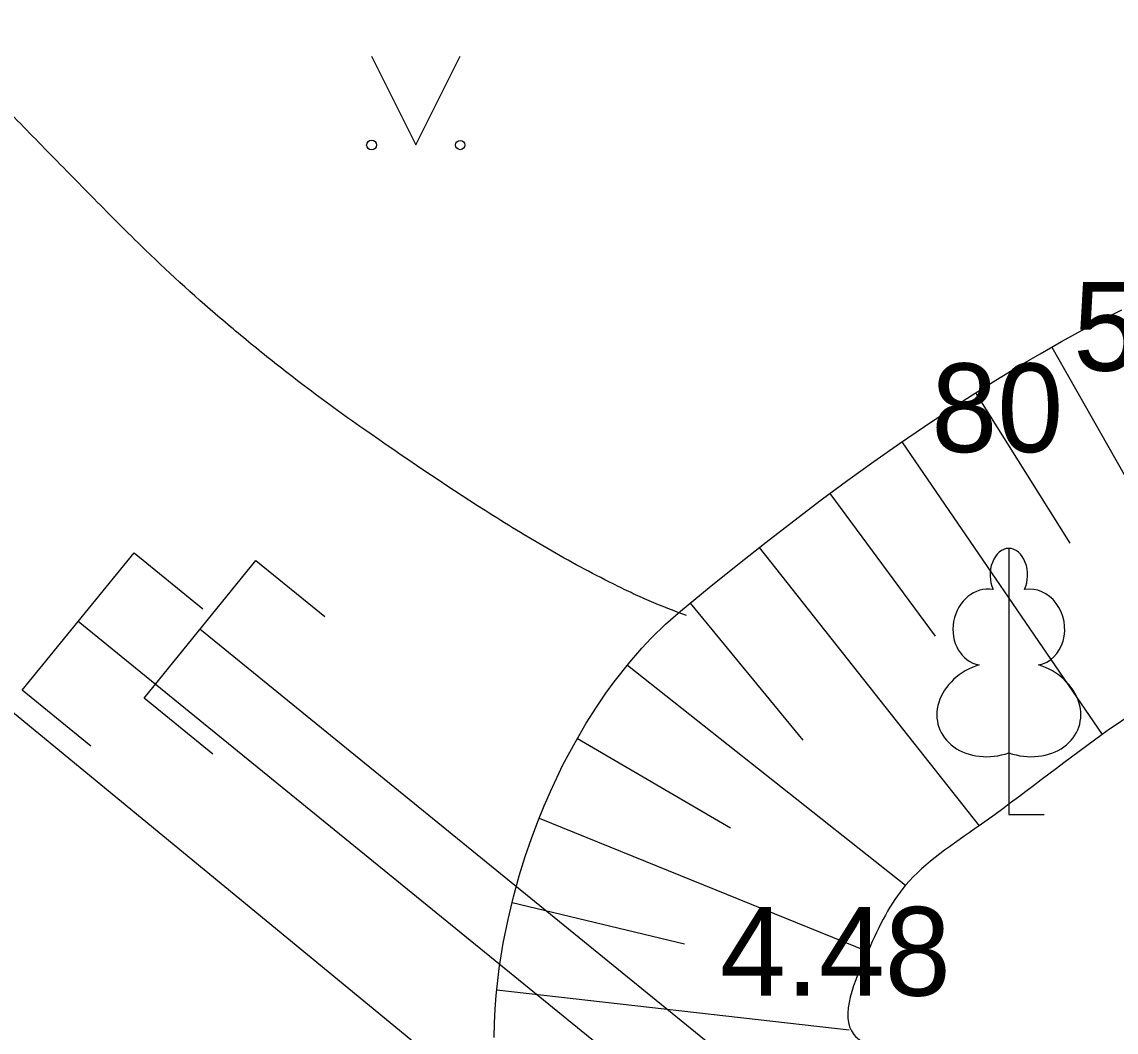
# Model space of a CAD drawing. Extents: x 519536 to 519949, y 326041 to 326519.
# Drawn here: x 519745.28 to 519751.45, y 326177.5 to 326183.19 of the extents above; entities that cross this region are included whole.
import ezdxf

# ---------------------------------------------------------------- set-up
doc = ezdxf.new("R2010")
doc.units = 0
for name, color, linetype in [('APGR_SARK_####_####_#', 7, 'Continuous'), ('RELJ_AATZ_####_TKST_#', 7, 'Continuous'), ('RELJ_HORZ_PAMT_####_#', 7, 'Continuous'), ('RELJ_NOGA_####_####_#', 7, 'Continuous'), ('RELJ_NOGL_####_####_#', 7, 'Continuous'), ('TERT_DIAM_####_TKST_#', 7, 'Continuous'), ('TERT_ELEM_####_####_#', 7, 'Continuous'), ('UDTK_ELEM_####_####_#', 7, 'Continuous'), ('UDTK_VADP_UDEN_####_#', 7, 'Continuous')]:
    doc.layers.add(name, color=color, linetype=linetype)

msp = doc.modelspace()

# ---------------------------------------------------------------- linework, layer by layer
at = {"layer": 'APGR_SARK_####_####_#'}
msp.add_line((519731.6966, 326190.4297), (519783.534, 326147.79), dxfattribs=at)
at = {"layer": 'RELJ_HORZ_PAMT_####_#'}
msp.add_spline([(519749.0249, 326179.8463), (519748.8152, 326179.9287), (519748.7125, 326179.9755), (519748.611, 326180.0251), (519748.2448, 326180.222), (519747.8902, 326180.4382), (519747.2053, 326180.8982), (519746.8687, 326181.142), (519746.6298, 326181.3297), (519746.3962, 326181.5235), (519745.9484, 326181.9329), (519745.6679, 326182.2133), (519745.3903, 326182.4964), (519745.1131, 326182.7799), (519744.834, 326183.0614), (519744.2703, 326183.622), (519743.9852, 326183.8991), (519743.697, 326184.1733), (519743.3895, 326184.4388), (519743.0687, 326184.6887), (519742.9015, 326184.8147), (519742.7312, 326184.9364), (519742.5556, 326185.0509), (519742.3728, 326185.1586), (519742.334, 326185.1795)], degree=3, dxfattribs=at)
at = {"layer": 'RELJ_NOGA_####_####_#'}
for p, q in [((519751.085, 326181.36), (519752.072, 326179.621)), ((519750.656, 326181.102), (519751.187, 326180.255)), ((519750.24, 326180.826), (519751.369, 326179.175)), ((519749.833, 326180.534), (519750.428, 326179.73)), ((519749.436, 326180.231), (519750.676, 326178.661)), ((519749.047, 326179.917), (519749.682, 326179.144)), ((519748.692, 326179.566), (519750.261, 326178.326)), ((519748.41, 326179.154), (519749.273, 326178.65)), ((519748.194, 326178.703), (519750.048, 326177.953)), ((519748.042, 326178.228), (519749.014, 326177.995)), ((519747.955, 326177.736), (519749.943, 326177.511))]:
    msp.add_line(p, q, dxfattribs=at)
msp.add_lwpolyline([(519747.94, 326177.467), (519747.942, 326177.548), (519747.946, 326177.627), (519747.952, 326177.704), (519747.969, 326177.856), (519747.992, 326177.999), (519748.019, 326178.133), (519748.049, 326178.26), (519748.082, 326178.378), (519748.116, 326178.488), (519748.151, 326178.59), (519748.187, 326178.685), (519748.222, 326178.773), (519748.258, 326178.854), (519748.329, 326179.004), (519748.397, 326179.131), (519748.459, 326179.239), (519748.517, 326179.33), (519748.57, 326179.408), (519748.618, 326179.473), (519748.705, 326179.584), (519748.773, 326179.662), (519748.826, 326179.718), (519748.907, 326179.797), (519748.991, 326179.871), (519749.154, 326180.005), (519749.315, 326180.135), (519749.474, 326180.26), (519749.63, 326180.381), (519749.784, 326180.498), (519749.935, 326180.609), (519750.082, 326180.715), (519750.226, 326180.817), (519750.367, 326180.913), (519750.505, 326181.005), (519750.639, 326181.091), (519750.769, 326181.173), (519750.896, 326181.25), (519751.02, 326181.323), (519751.14, 326181.391), (519751.257, 326181.455), (519751.37, 326181.515), (519751.48, 326181.57)], dxfattribs=at)
msp.add_lwpolyline([(519747.94, 326177.467), (519747.942, 326177.548), (519747.946, 326177.627), (519747.952, 326177.704), (519747.969, 326177.856), (519747.992, 326177.999), (519748.019, 326178.133), (519748.049, 326178.26), (519748.082, 326178.378), (519748.116, 326178.488), (519748.151, 326178.59), (519748.187, 326178.685), (519748.222, 326178.773), (519748.258, 326178.854), (519748.329, 326179.004), (519748.397, 326179.131), (519748.459, 326179.239), (519748.517, 326179.33), (519748.57, 326179.408), (519748.618, 326179.473), (519748.705, 326179.584), (519748.773, 326179.662), (519748.826, 326179.718), (519748.907, 326179.797), (519748.991, 326179.871), (519749.154, 326180.005), (519749.315, 326180.135), (519749.474, 326180.26), (519749.63, 326180.381), (519749.784, 326180.498), (519749.935, 326180.609), (519750.082, 326180.715), (519750.226, 326180.817), (519750.367, 326180.913), (519750.505, 326181.005), (519750.639, 326181.091), (519750.769, 326181.173), (519750.896, 326181.25), (519751.02, 326181.323), (519751.14, 326181.391), (519751.257, 326181.455), (519751.37, 326181.515), (519751.48, 326181.57)], dxfattribs=at)
msp.add_lwpolyline([(519747.94, 326177.467), (519747.942, 326177.548), (519747.946, 326177.627), (519747.952, 326177.704), (519747.969, 326177.856), (519747.992, 326177.999), (519748.019, 326178.133), (519748.049, 326178.26), (519748.082, 326178.378), (519748.116, 326178.488), (519748.151, 326178.59), (519748.187, 326178.685), (519748.222, 326178.773), (519748.258, 326178.854), (519748.329, 326179.004), (519748.397, 326179.131), (519748.459, 326179.239), (519748.517, 326179.33), (519748.57, 326179.408), (519748.618, 326179.473), (519748.705, 326179.584), (519748.773, 326179.662), (519748.826, 326179.718), (519748.907, 326179.797), (519748.991, 326179.871), (519749.154, 326180.005), (519749.315, 326180.135), (519749.474, 326180.26), (519749.63, 326180.381), (519749.784, 326180.498), (519749.935, 326180.609), (519750.082, 326180.715), (519750.226, 326180.817), (519750.367, 326180.913), (519750.505, 326181.005), (519750.639, 326181.091), (519750.769, 326181.173), (519750.896, 326181.25), (519751.02, 326181.323), (519751.14, 326181.391), (519751.257, 326181.455), (519751.37, 326181.515), (519751.48, 326181.57)], dxfattribs=at)
msp.add_lwpolyline([(519747.94, 326177.467), (519747.942, 326177.548), (519747.946, 326177.627), (519747.952, 326177.704), (519747.969, 326177.856), (519747.992, 326177.999), (519748.019, 326178.133), (519748.049, 326178.26), (519748.082, 326178.378), (519748.116, 326178.488), (519748.151, 326178.59), (519748.187, 326178.685), (519748.222, 326178.773), (519748.258, 326178.854), (519748.329, 326179.004), (519748.397, 326179.131), (519748.459, 326179.239), (519748.517, 326179.33), (519748.57, 326179.408), (519748.618, 326179.473), (519748.705, 326179.584), (519748.773, 326179.662), (519748.826, 326179.718), (519748.907, 326179.797), (519748.991, 326179.871), (519749.154, 326180.005), (519749.315, 326180.135), (519749.474, 326180.26), (519749.63, 326180.381), (519749.784, 326180.498), (519749.935, 326180.609), (519750.082, 326180.715), (519750.226, 326180.817), (519750.367, 326180.913), (519750.505, 326181.005), (519750.639, 326181.091), (519750.769, 326181.173), (519750.896, 326181.25), (519751.02, 326181.323), (519751.14, 326181.391), (519751.257, 326181.455), (519751.37, 326181.515), (519751.48, 326181.57)], dxfattribs=at)
msp.add_lwpolyline([(519747.94, 326177.467), (519747.942, 326177.548), (519747.946, 326177.627), (519747.952, 326177.704), (519747.969, 326177.856), (519747.992, 326177.999), (519748.019, 326178.133), (519748.049, 326178.26), (519748.082, 326178.378), (519748.116, 326178.488), (519748.151, 326178.59), (519748.187, 326178.685), (519748.222, 326178.773), (519748.258, 326178.854), (519748.329, 326179.004), (519748.397, 326179.131), (519748.459, 326179.239), (519748.517, 326179.33), (519748.57, 326179.408), (519748.618, 326179.473), (519748.705, 326179.584), (519748.773, 326179.662), (519748.826, 326179.718), (519748.907, 326179.797), (519748.991, 326179.871), (519749.154, 326180.005), (519749.315, 326180.135), (519749.474, 326180.26), (519749.63, 326180.381), (519749.784, 326180.498), (519749.935, 326180.609), (519750.082, 326180.715), (519750.226, 326180.817), (519750.367, 326180.913), (519750.505, 326181.005), (519750.639, 326181.091), (519750.769, 326181.173), (519750.896, 326181.25), (519751.02, 326181.323), (519751.14, 326181.391), (519751.257, 326181.455), (519751.37, 326181.515), (519751.48, 326181.57)], dxfattribs=at)
msp.add_lwpolyline([(519747.94, 326177.467), (519747.942, 326177.548), (519747.946, 326177.627), (519747.952, 326177.704), (519747.969, 326177.856), (519747.992, 326177.999), (519748.019, 326178.133), (519748.049, 326178.26), (519748.082, 326178.378), (519748.116, 326178.488), (519748.151, 326178.59), (519748.187, 326178.685), (519748.222, 326178.773), (519748.258, 326178.854), (519748.329, 326179.004), (519748.397, 326179.131), (519748.459, 326179.239), (519748.517, 326179.33), (519748.57, 326179.408), (519748.618, 326179.473), (519748.705, 326179.584), (519748.773, 326179.662), (519748.826, 326179.718), (519748.907, 326179.797), (519748.991, 326179.871), (519749.154, 326180.005), (519749.315, 326180.135), (519749.474, 326180.26), (519749.63, 326180.381), (519749.784, 326180.498), (519749.935, 326180.609), (519750.082, 326180.715), (519750.226, 326180.817), (519750.367, 326180.913), (519750.505, 326181.005), (519750.639, 326181.091), (519750.769, 326181.173), (519750.896, 326181.25), (519751.02, 326181.323), (519751.14, 326181.391), (519751.257, 326181.455), (519751.37, 326181.515), (519751.48, 326181.57)], dxfattribs=at)
msp.add_lwpolyline([(519747.94, 326177.467), (519747.942, 326177.548), (519747.946, 326177.627), (519747.952, 326177.704), (519747.969, 326177.856), (519747.992, 326177.999), (519748.019, 326178.133), (519748.049, 326178.26), (519748.082, 326178.378), (519748.116, 326178.488), (519748.151, 326178.59), (519748.187, 326178.685), (519748.222, 326178.773), (519748.258, 326178.854), (519748.329, 326179.004), (519748.397, 326179.131), (519748.459, 326179.239), (519748.517, 326179.33), (519748.57, 326179.408), (519748.618, 326179.473), (519748.705, 326179.584), (519748.773, 326179.662), (519748.826, 326179.718), (519748.907, 326179.797), (519748.991, 326179.871), (519749.154, 326180.005), (519749.315, 326180.135), (519749.474, 326180.26), (519749.63, 326180.381), (519749.784, 326180.498), (519749.935, 326180.609), (519750.082, 326180.715), (519750.226, 326180.817), (519750.367, 326180.913), (519750.505, 326181.005), (519750.639, 326181.091), (519750.769, 326181.173), (519750.896, 326181.25), (519751.02, 326181.323), (519751.14, 326181.391), (519751.257, 326181.455), (519751.37, 326181.515), (519751.48, 326181.57)], dxfattribs=at)
msp.add_lwpolyline([(519747.94, 326177.467), (519747.942, 326177.548), (519747.946, 326177.627), (519747.952, 326177.704), (519747.969, 326177.856), (519747.992, 326177.999), (519748.019, 326178.133), (519748.049, 326178.26), (519748.082, 326178.378), (519748.116, 326178.488), (519748.151, 326178.59), (519748.187, 326178.685), (519748.222, 326178.773), (519748.258, 326178.854), (519748.329, 326179.004), (519748.397, 326179.131), (519748.459, 326179.239), (519748.517, 326179.33), (519748.57, 326179.408), (519748.618, 326179.473), (519748.705, 326179.584), (519748.773, 326179.662), (519748.826, 326179.718), (519748.907, 326179.797), (519748.991, 326179.871), (519749.154, 326180.005), (519749.315, 326180.135), (519749.474, 326180.26), (519749.63, 326180.381), (519749.784, 326180.498), (519749.935, 326180.609), (519750.082, 326180.715), (519750.226, 326180.817), (519750.367, 326180.913), (519750.505, 326181.005), (519750.639, 326181.091), (519750.769, 326181.173), (519750.896, 326181.25), (519751.02, 326181.323), (519751.14, 326181.391), (519751.257, 326181.455), (519751.37, 326181.515), (519751.48, 326181.57)], dxfattribs=at)
msp.add_lwpolyline([(519747.94, 326177.467), (519747.942, 326177.548), (519747.946, 326177.627), (519747.952, 326177.704), (519747.969, 326177.856), (519747.992, 326177.999), (519748.019, 326178.133), (519748.049, 326178.26), (519748.082, 326178.378), (519748.116, 326178.488), (519748.151, 326178.59), (519748.187, 326178.685), (519748.222, 326178.773), (519748.258, 326178.854), (519748.329, 326179.004), (519748.397, 326179.131), (519748.459, 326179.239), (519748.517, 326179.33), (519748.57, 326179.408), (519748.618, 326179.473), (519748.705, 326179.584), (519748.773, 326179.662), (519748.826, 326179.718), (519748.907, 326179.797), (519748.991, 326179.871), (519749.154, 326180.005), (519749.315, 326180.135), (519749.474, 326180.26), (519749.63, 326180.381), (519749.784, 326180.498), (519749.935, 326180.609), (519750.082, 326180.715), (519750.226, 326180.817), (519750.367, 326180.913), (519750.505, 326181.005), (519750.639, 326181.091), (519750.769, 326181.173), (519750.896, 326181.25), (519751.02, 326181.323), (519751.14, 326181.391), (519751.257, 326181.455), (519751.37, 326181.515), (519751.48, 326181.57)], dxfattribs=at)
msp.add_lwpolyline([(519747.94, 326177.467), (519747.942, 326177.548), (519747.946, 326177.627), (519747.952, 326177.704), (519747.969, 326177.856), (519747.992, 326177.999), (519748.019, 326178.133), (519748.049, 326178.26), (519748.082, 326178.378), (519748.116, 326178.488), (519748.151, 326178.59), (519748.187, 326178.685), (519748.222, 326178.773), (519748.258, 326178.854), (519748.329, 326179.004), (519748.397, 326179.131), (519748.459, 326179.239), (519748.517, 326179.33), (519748.57, 326179.408), (519748.618, 326179.473), (519748.705, 326179.584), (519748.773, 326179.662), (519748.826, 326179.718), (519748.907, 326179.797), (519748.991, 326179.871), (519749.154, 326180.005), (519749.315, 326180.135), (519749.474, 326180.26), (519749.63, 326180.381), (519749.784, 326180.498), (519749.935, 326180.609), (519750.082, 326180.715), (519750.226, 326180.817), (519750.367, 326180.913), (519750.505, 326181.005), (519750.639, 326181.091), (519750.769, 326181.173), (519750.896, 326181.25), (519751.02, 326181.323), (519751.14, 326181.391), (519751.257, 326181.455), (519751.37, 326181.515), (519751.48, 326181.57)], dxfattribs=at)
msp.add_lwpolyline([(519747.94, 326177.467), (519747.942, 326177.548), (519747.946, 326177.627), (519747.952, 326177.704), (519747.969, 326177.856), (519747.992, 326177.999), (519748.019, 326178.133), (519748.049, 326178.26), (519748.082, 326178.378), (519748.116, 326178.488), (519748.151, 326178.59), (519748.187, 326178.685), (519748.222, 326178.773), (519748.258, 326178.854), (519748.329, 326179.004), (519748.397, 326179.131), (519748.459, 326179.239), (519748.517, 326179.33), (519748.57, 326179.408), (519748.618, 326179.473), (519748.705, 326179.584), (519748.773, 326179.662), (519748.826, 326179.718), (519748.907, 326179.797), (519748.991, 326179.871), (519749.154, 326180.005), (519749.315, 326180.135), (519749.474, 326180.26), (519749.63, 326180.381), (519749.784, 326180.498), (519749.935, 326180.609), (519750.082, 326180.715), (519750.226, 326180.817), (519750.367, 326180.913), (519750.505, 326181.005), (519750.639, 326181.091), (519750.769, 326181.173), (519750.896, 326181.25), (519751.02, 326181.323), (519751.14, 326181.391), (519751.257, 326181.455), (519751.37, 326181.515), (519751.48, 326181.57)], dxfattribs=at)
msp.add_lwpolyline([(519747.94, 326177.467), (519747.942, 326177.548), (519747.946, 326177.627), (519747.952, 326177.704), (519747.969, 326177.856), (519747.992, 326177.999), (519748.019, 326178.133), (519748.049, 326178.26), (519748.082, 326178.378), (519748.116, 326178.488), (519748.151, 326178.59), (519748.187, 326178.685), (519748.222, 326178.773), (519748.258, 326178.854), (519748.329, 326179.004), (519748.397, 326179.131), (519748.459, 326179.239), (519748.517, 326179.33), (519748.57, 326179.408), (519748.618, 326179.473), (519748.705, 326179.584), (519748.773, 326179.662), (519748.826, 326179.718), (519748.907, 326179.797), (519748.991, 326179.871), (519749.154, 326180.005), (519749.315, 326180.135), (519749.474, 326180.26), (519749.63, 326180.381), (519749.784, 326180.498), (519749.935, 326180.609), (519750.082, 326180.715), (519750.226, 326180.817), (519750.367, 326180.913), (519750.505, 326181.005), (519750.639, 326181.091), (519750.769, 326181.173), (519750.896, 326181.25), (519751.02, 326181.323), (519751.14, 326181.391), (519751.257, 326181.455), (519751.37, 326181.515), (519751.48, 326181.57)], dxfattribs=at)
at = {"layer": 'RELJ_NOGL_####_####_#'}
msp.add_spline([(519750.737, 326177.254), (519750.215, 326177.377), (519749.969, 326177.484), (519750.048, 326177.953), (519750.261, 326178.326), (519750.676, 326178.661), (519751.369, 326179.175), (519752.072, 326179.621), (519752.69, 326179.926), (519753.234, 326180.089), (519753.479, 326180.102), (519753.717, 326179.972), (519754.546, 326179.412), (519755.374, 326178.852), (519756.203, 326178.292), (519757.672, 326177.735), (519758.639, 326177.481), (519759.607, 326177.228), (519760.574, 326176.974), (519761.541, 326176.72), (519762.508, 326176.467), (519763.476, 326176.213), (519764.443, 326175.959), (519765.393, 326175.925), (519765.768, 326175.898), (519766.265, 326175.777), (519766.935, 326175.588), (519767.042, 326175.305), (519766.305, 326175.453), (519765.567, 326175.211), (519764.648, 326175.432), (519763.823, 326175.243), (519762.834, 326175.091), (519761.846, 326174.939), (519761.533, 326174.895), (519760.55, 326175.08), (519759.567, 326175.264), (519758.585, 326175.449), (519757.602, 326175.634), (519756.619, 326175.819), (519755.636, 326176.003), (519754.653, 326176.188), (519753.671, 326176.373), (519752.688, 326176.558), (519752.282, 326176.749), (519751.361, 326177.138), (519750.737, 326177.254)], degree=3, dxfattribs=at)
at = {"layer": 'TERT_ELEM_####_####_#'}
for p, q in [((519747.25, 326183), (519747.5, 326182.5)), ((519747.5, 326182.5), (519747.75, 326183)), ((519750.843, 326179.072), (519750.843, 326178.725)), ((519750.843, 326178.725), (519751.043, 326178.725))]:
    msp.add_line(p, q, dxfattribs=at)
for points in [[(519750.843, 326180.225), (519750.843, 326179.072)], [(519750.9326, 326179.9926), (519750.9316, 326179.9935)]]:
    msp.add_lwpolyline(points, dxfattribs=at)
for centre, radius in [((519747.2497, 326182.4995), 0.028), ((519747.7497, 326182.4995), 0.0263)]:
    msp.add_circle(centre, radius, dxfattribs=at)
for centre, major_axis, ratio, start_param, end_param in [((519750.8434, 326180.0751), (0, -0.1499), 0.707107, 3.14537, 5.287485), ((519750.8426, 326180.0751), (0, -0.1499), 0.707107, 0.995701, 3.137816), ((519750.7147, 326179.7802), (-0.0387, -0.2124), 0.861323, 3.141593, 6.283185), ((519750.9713, 326179.7802), (0.0387, -0.2124), 0.861323, 0, 3.141593), ((519750.7534, 326179.3179), (0.3068, 0.0951), 0.814445, 1.570796, 4.752015), ((519750.9326, 326179.3179), (-0.3068, 0.0951), 0.814445, 1.531171, 4.712389)]:
    msp.add_ellipse(centre, major_axis=major_axis, ratio=ratio, start_param=start_param, end_param=end_param, dxfattribs=at)
at = {"layer": 'UDTK_ELEM_####_####_#'}
for points in [[(519745.6672, 326179.1096), (519745.2794, 326179.4252), (519745.9106, 326180.2008), (519746.2984, 326179.8852)], [(519746.3542, 326179.0656), (519745.9664, 326179.3812), (519746.5976, 326180.1568), (519746.9854, 326179.8412)]]:
    msp.add_lwpolyline(points, dxfattribs=at)
at = {"layer": 'UDTK_VADP_UDEN_####_#'}
for points in [[(519767.2029, 326162.2301), (519745.595, 326179.813)], [(519767.4702, 326162.5276), (519746.282, 326179.769)]]:
    msp.add_lwpolyline(points, dxfattribs=at)

# ---------------------------------------------------------------- texts
at = {"layer": 'RELJ_AATZ_####_TKST_#'}
msp.add_text('4.48', height=0.5, dxfattribs=at).set_placement((519749.214, 326177.703))
at = {"layer": 'TERT_DIAM_####_TKST_#'}
for s, p in [('55', (519751.206, 326181.227)), ('80', (519750.406, 326180.768))]:
    msp.add_text(s, height=0.5, dxfattribs=at).set_placement(p)

doc.saveas('drawing.dxf')
